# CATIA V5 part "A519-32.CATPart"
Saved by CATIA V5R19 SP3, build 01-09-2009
Part number: A519-32
Bounding box of the stored display mesh (mm): x -15.996 to 15.996, y -15.996 to 15.996, z 0 to 50
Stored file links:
  C:\Users\d.catalano\Desktop\CATALOGO CAD\04 MOLLE\A519\A519-32.CATPart
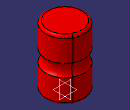
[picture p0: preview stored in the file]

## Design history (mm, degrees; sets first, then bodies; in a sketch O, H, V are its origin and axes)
Body1 "A519-32" (main body)
  Sketch1 on yz-plane, origin (0, 0, 0), H (0, 1, 0), V (0, 0, 1)
    line L1 (0, 0) -> (14, 0)
    line L2 (16, 2) -> (16, 19.9049)
    line L3 (14, 50) -> (0, 50)
    line L4 (0, 50) -> (0, 0)
    construction line L5 (-5.6038, 25) -> (28.5463, 25)
    arc A1 centre (20.8, 25) radius 7 from (16, 30.0951) to (16, 19.9049) ccw
    point P2 (20.8, 25)
    construction line L6 (13.8, 49.6338) -> (13.8, -12.4196)
    line L7 (16, 30.0951) -> (16, 48)
    arc A2 centre (14, 48) radius 2 from (14, 50) to (16, 48) cw
    arc A3 centre (14, 2) radius 2 from (14, 0) to (16, 2) ccw
    distance L4 L2 = 16
    distance L1 L3 = 50
    distance L5 L3 = 25
    radius A1 = 7
    distance L2 L6 = 2.2
    radius A2 = 2
    radius A3 = 2
    horizontal: L1 H, L3 H, L5 H
    vertical: L2 V, L4 V, L6 V, L7 V
    coincidence: P2 L5, L2 L7
    tangency: A1 L6, A2 L3, A2 L7, A3 L1, A3 L2
  Shaft1 "Albero": profile Sketch1, axis Sketch1.L4, angle 360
